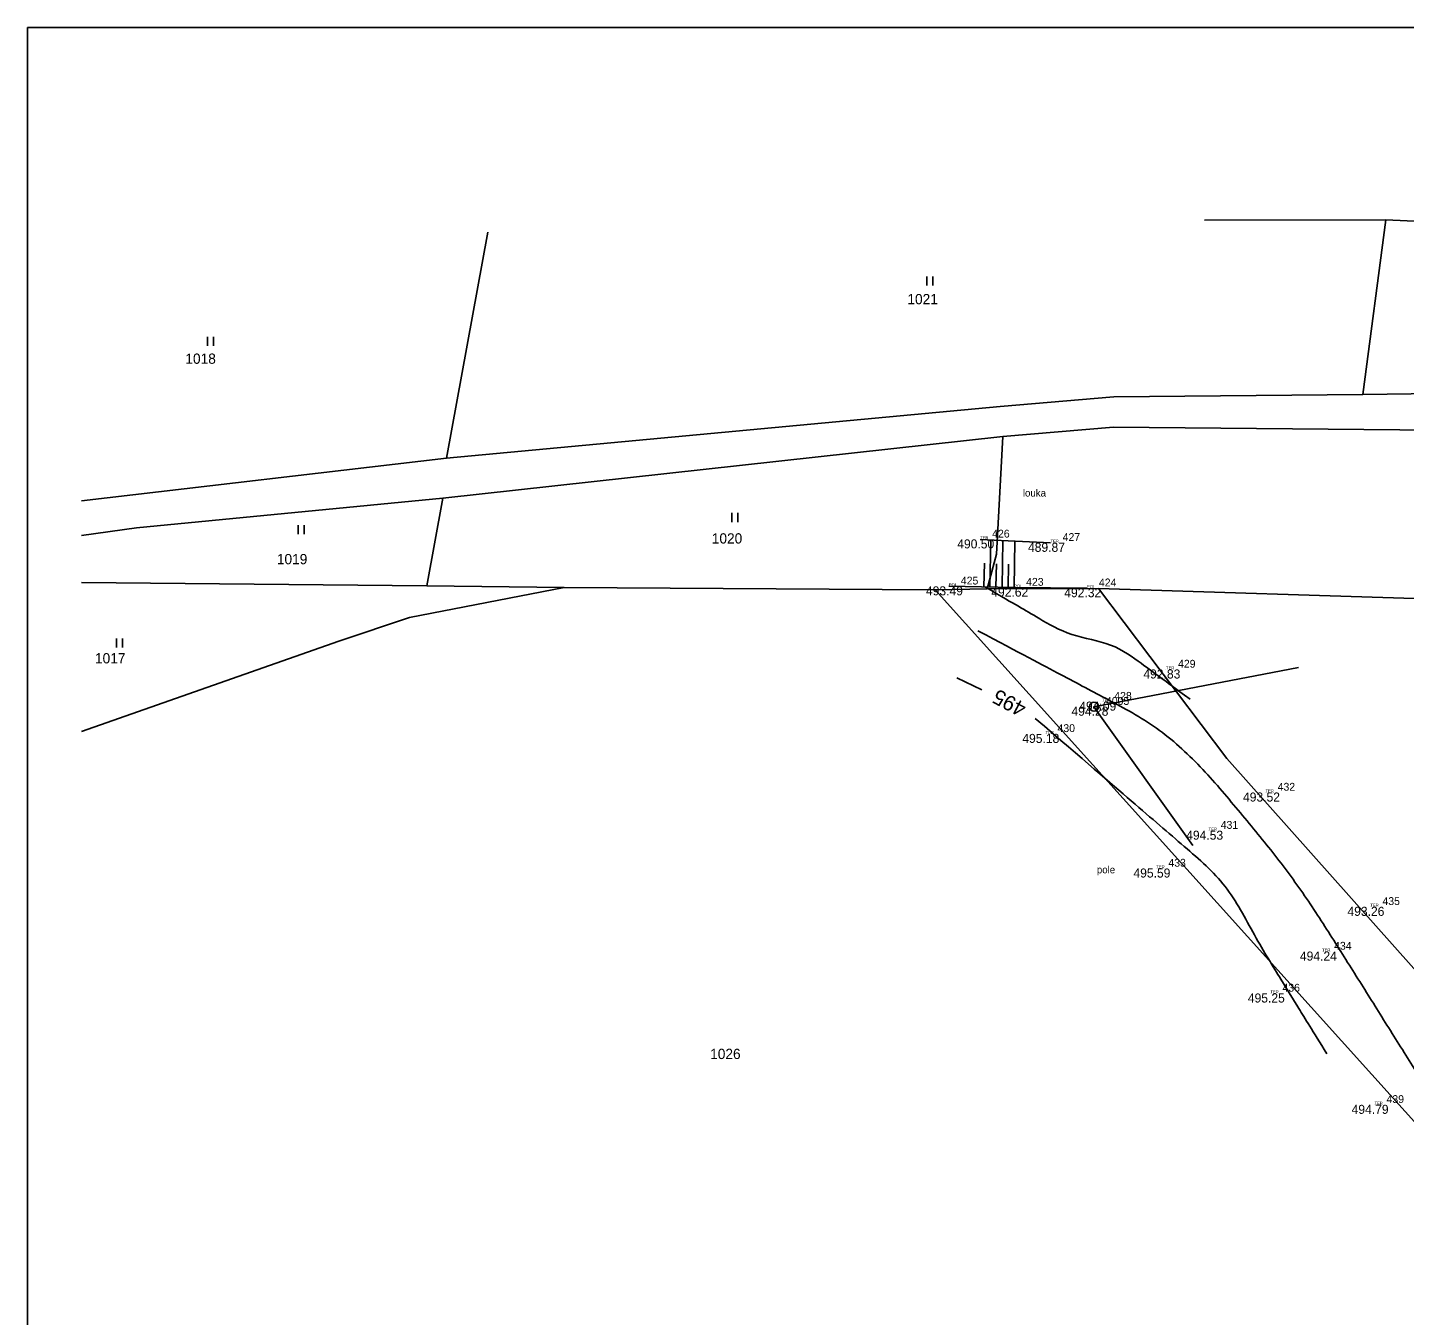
# Model space of a CAD drawing. Extents: x -604848 to -603227, y -1111879 to -1109838.
# Drawn here: x -604346.1 to -604117.6, y -1110051.5 to -1109837.8 of the extents above; entities that cross this region are included whole.
import ezdxf

# ---------------------------------------------------------------- set-up
doc = ezdxf.new("R2010")
doc.units = 0
for name, color, linetype in [('1', 7, 'Continuous'), ('10', 7, 'Continuous'), ('14', 7, 'Continuous'), ('18', 7, 'Continuous'), ('19', 7, 'Continuous'), ('20', 7, 'Continuous'), ('23', 7, 'Continuous'), ('5', 7, 'Continuous'), ('7', 7, 'Continuous'), ('8', 7, 'Continuous'), ('9', 7, 'Continuous'), ('Default', 7, 'Continuous')]:
    doc.layers.add(name, color=color, linetype=linetype)

# ---------------------------------------------------------------- blocks, each defined once
blk = doc.blocks.new('Z3060')
at = {"layer": '23'}
for p, q in [((-0.5, 0), (-0.5, 1.5)), ((0.5, 1.5), (0.5, 0))]:
    blk.add_line(p, q, dxfattribs=at)
blk = doc.blocks.new('POINT_DISPLAY')
at = {"layer": 'Default'}
blk.add_line((0, 0), (0, 0), dxfattribs=at)
blk = doc.blocks.new('Z107')
at = {"layer": '5'}
for radius in [0.75, 0.01]:
    blk.add_circle((0, 0), radius, dxfattribs=at)

msp = doc.modelspace()

# ---------------------------------------------------------------- linework, layer by layer
at = {"layer": '1'}
for p, q in [((-604120.68, -1109869.74), (-604150.74, -1109869.77)), ((-604124.47, -1109898.69), (-604120.68, -1109869.74)), ((-604106.62, -1109870.34), (-604120.68, -1109869.74)), ((-604276.54, -1109909.27), (-604269.68, -1109871.79)), ((-604184.65, -1109900.71), (-604165.79, -1109899.11)), ((-604165.79, -1109899.11), (-604124.47, -1109898.69)), ((-604124.47, -1109898.69), (-604084.8, -1109898.15)), ((-604276.54, -1109909.27), (-604184.65, -1109900.71)), ((-604165.84, -1109904.11), (-604184.2, -1109905.68)), ((-604091.9, -1109904.81), (-604165.84, -1109904.11)), ((-604277.14, -1109915.9), (-604184.2, -1109905.68)), ((-604184.2, -1109905.68), (-604185.26, -1109925.22)), ((-604337.1, -1109916.33), (-604276.54, -1109909.27)), ((-604277.14, -1109915.9), (-604327.97, -1109920.86)), ((-604279.77, -1109930.47), (-604277.14, -1109915.9)), ((-604327.97, -1109920.86), (-604337.1, -1109922.09)), ((-604185.26, -1109925.22), (-604186.81, -1109930.94)), ((-604337.1, -1109929.93), (-604279.77, -1109930.47)), ((-604282.68, -1109935.73), (-604256.99, -1109930.76)), ((-604256.99, -1109930.76), (-604279.77, -1109930.47)), ((-604195.43, -1109931.12), (-604256.99, -1109930.76)), ((-604186.81, -1109930.94), (-604195.43, -1109931.12)), ((-604102.57, -1110034.26), (-604195.43, -1109931.12)), ((-604186.81, -1109930.94), (-604168.34, -1109930.89)), ((-604168.34, -1109930.89), (-604147.03, -1109959.11)), ((-604168.34, -1109930.89), (-604043.08, -1109934.91)), ((-604294.37, -1109939.66), (-604282.68, -1109935.73)), ((-604337.1, -1109954.63), (-604294.37, -1109939.66)), ((-604147.03, -1109959.11), (-604090.17, -1110023.09))]:
    msp.add_line(p, q, dxfattribs=at)
msp.add_lwpolyline([(-603752.05, -1110677.81), (-603752.05, -1109837.81), (-604346.05, -1109837.81), (-604346.05, -1110677.81), (-603752.05, -1110677.81)], dxfattribs=at)
at = {"layer": '10'}
for p, q in [((-604182.35, -1109930.75), (-604193.18, -1109930.54)), ((-604170.27, -1109930.85), (-604182.35, -1109930.75))]:
    msp.add_line(p, q, dxfattribs=at)
at = {"layer": '5'}
for q in [(-604135.16, -1109944.04), (-604152.69, -1109973.55)]:
    msp.add_line((-604169.1, -1109950.52), q, dxfattribs=at)
at = {"layer": '7'}
for p, q in [((-604176.29, -1109923.32), (-604187.98, -1109922.75)), ((-604187.7, -1109947.7), (-604191.83, -1109945.74))]:
    msp.add_line(p, q, dxfattribs=at)
for points in [[(-604153.15, -1109949.27), (-604155.7, -1109947.4), (-604158.26, -1109945.52), (-604160.82, -1109943.64), (-604166.04, -1109939.8), (-604172.96, -1109938.94), (-604178.56, -1109935.66), (-604181.4, -1109933.99), (-604184.25, -1109932.33), (-604187.1, -1109930.66)], [(-604096.53, -1110048.04), (-604098.4, -1110042.67), (-604100.25, -1110037.29), (-604102.12, -1110031.91), (-604104.84, -1110024.09), (-604111.2, -1110018.05), (-604115.63, -1110011.05), (-604120.2, -1110003.83), (-604124.7, -1109996.56), (-604129.28, -1109989.34), (-604134.06, -1109981.81), (-604139.33, -1109974.7), (-604145.1, -1109967.77), (-604151.28, -1109960.36), (-604158.5, -1109953.74), (-604166.92, -1109949.27), (-604174.06, -1109945.49), (-604181.2, -1109941.71), (-604188.34, -1109937.93)], [(-604130.45, -1110008.13), (-604132.87, -1110004.21), (-604135.28, -1110000.3), (-604137.69, -1109996.39), (-604142.54, -1109988.52), (-604146.9, -1109979.91), (-604153.91, -1109973.88), (-604162.21, -1109966.74), (-604170.52, -1109959.6), (-604178.83, -1109952.46)]]:
    msp.add_open_spline(points, degree=3, dxfattribs=at)
at = {"layer": '8'}
for p, q in [((-604186.35, -1109930.67), (-604186.19, -1109922.83)), ((-604184.35, -1109930.71), (-604184.19, -1109922.93)), ((-604182.35, -1109930.75), (-604182.2, -1109923.03)), ((-604187.35, -1109930.65), (-604187.27, -1109926.72)), ((-604185.35, -1109930.69), (-604185.27, -1109926.79)), ((-604183.35, -1109930.73), (-604183.27, -1109926.86))]:
    msp.add_line(p, q, dxfattribs=at)

# ---------------------------------------------------------------- block references
at = {"layer": '18'}
for p in [(-604187.98, -1109922.75), (-604176.29, -1109923.32), (-604193.18, -1109930.54), (-604182.35, -1109930.75), (-604170.27, -1109930.85), (-604157.14, -1109944.34), (-604167.72, -1109949.67), (-604169.1, -1109950.52), (-604177.14, -1109955.03), (-604140.61, -1109964.76), (-604150.06, -1109971.09), (-604158.74, -1109977.37), (-604123.22, -1109983.73), (-604131.24, -1109991.15), (-604139.81, -1109998.11), (-604122.54, -1110016.59)]:
    msp.add_blockref('POINT_DISPLAY', p, dxfattribs=at)
at = {"layer": '23'}
for p in [(-604196.34, -1109880.61), (-604315.68, -1109890.66), (-604228.7, -1109919.87), (-604300.67, -1109921.88), (-604330.8, -1109940.69)]:
    msp.add_blockref('Z3060', p, dxfattribs=at)
at = {"layer": '5'}
msp.add_blockref('Z107', (-604169.1, -1109950.52), dxfattribs=at)

# ---------------------------------------------------------------- texts
at = {"layer": '14'}
for s, p in [('1021', (-604200.05, -1109883.73)), ('1018', (-604319.86, -1109893.61)), ('1020', (-604232.51, -1109923.44)), ('1019', (-604304.68, -1109926.88)), ('1017', (-604334.86, -1109943.33)), ('1026', (-604232.78, -1110008.99))]:
    msp.add_text(s, height=1.7, dxfattribs=at).set_placement(p)
at = {"layer": '18'}
for s, p in [('TER', (-604187.98, -1109922.75)), ('TER', (-604176.29, -1109923.32)), ('POL', (-604193.18, -1109930.54)), ('POL', (-604182.35, -1109930.75)), ('POL', (-604170.27, -1109930.85)), ('TER', (-604157.14, -1109944.34)), ('STA', (-604169.1, -1109950.52)), ('TER', (-604167.72, -1109949.67)), ('TER', (-604177.14, -1109955.03)), ('TER', (-604140.61, -1109964.76)), ('TER', (-604150.06, -1109971.09)), ('TER', (-604158.74, -1109977.37)), ('TER', (-604123.22, -1109983.73)), ('TER', (-604131.24, -1109991.15)), ('TER', (-604139.81, -1109998.11)), ('TER', (-604122.54, -1110016.59))]:
    msp.add_text(s, height=0.5, dxfattribs=at).set_placement(p)
at = {"layer": '19'}
for s, p in [('426', (-604185.98, -1109922.45)), ('427', (-604174.29, -1109923.02)), ('425', (-604191.18, -1109930.24)), ('423', (-604180.35, -1109930.45)), ('424', (-604168.27, -1109930.55)), ('429', (-604155.14, -1109944.04)), ('428', (-604165.72, -1109949.37)), ('4005', (-604167.1, -1109950.22)), ('430', (-604175.14, -1109954.73)), ('432', (-604138.61, -1109964.46)), ('431', (-604148.06, -1109970.79)), ('433', (-604156.74, -1109977.07)), ('435', (-604121.22, -1109983.43)), ('434', (-604129.24, -1109990.85)), ('436', (-604137.81, -1109997.81)), ('439', (-604120.54, -1110016.29))]:
    msp.add_text(s, height=1.3, dxfattribs=at).set_placement(p)
at = {"layer": '20'}
for s, p in [('490.50 ', (-604191.78, -1109924.25)), ('489.87 ', (-604180.04, -1109924.82)), ('493.49 ', (-604196.97, -1109932.04)), ('492.62 ', (-604186.13, -1109932.25)), ('492.32 ', (-604174.02, -1109932.35)), ('492.83 ', (-604160.89, -1109945.84)), ('494.09 ', (-604171.53, -1109951.17)), ('494.28 ', (-604172.83, -1109952.02)), ('495.18 ', (-604180.98, -1109956.53)), ('493.52 ', (-604144.36, -1109966.26)), ('494.53 ', (-604153.79, -1109972.59)), ('495.59 ', (-604162.54, -1109978.87)), ('493.26 ', (-604127.03, -1109985.23)), ('494.24 ', (-604134.92, -1109992.65)), ('495.25 ', (-604143.56, -1109999.61)), ('494.79 ', (-604126.34, -1110018.09))]:
    msp.add_text(s, height=1.5, dxfattribs=at).set_placement(p)
at = {"layer": '7'}
msp.add_text('495', height=2.5, rotation=152.1, dxfattribs=at).set_placement((-604180.09, -1109950.12))
at = {"layer": '9'}
for s, p in [('louka', (-604180.89, -1109915.64)), ('pole', (-604168.61, -1109978.17))]:
    msp.add_text(s, height=1.2, dxfattribs=at).set_placement(p)

doc.saveas('drawing.dxf')
